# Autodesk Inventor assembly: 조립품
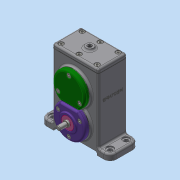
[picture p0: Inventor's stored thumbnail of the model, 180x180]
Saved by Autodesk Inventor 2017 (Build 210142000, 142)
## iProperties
Part Number: 조립품
Material: 일반
Document SubType Name: Assembly
Designer: 222
Mass: 1084.21 g
Surface Area: 1575.48 cm^2
Volume: 385.029 cm^3
Density: 2.81592 g/cm^3
Author: 222
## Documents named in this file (24)
- C:\Users\222\Desktop\600506V1061\조립품.iam
- C:\Users\222\Desktop\600506V1061\Ű 4 x 4 x 12.ipt
- C:\Users\222\Desktop\600506V1061\Ű 5 x 5 x 12.ipt
- C:\Users\222\Desktop\600506V1061\개스킷 A.ipt
- C:\Users\222\Desktop\600506V1061\개스킷 B.ipt
- C:\Users\222\Desktop\600506V1061\개스킷 C.ipt
- C:\Users\222\Desktop\600506V1061\베어링 6001.ipt
- 베어링 6001.ipt
- C:\Users\222\Desktop\600506V1061\베어링 6002.ipt
- 베어링 6002.ipt
- C:\Users\222\Desktop\600506V1061\본체.ipt
- C:\Users\222\Desktop\600506V1061\볼트 M4.ipt
- C:\Users\222\Desktop\600506V1061\스퍼기어 A.ipt
- C:\Users\222\Desktop\600506V1061\스퍼기어 B.ipt
- C:\Users\222\Desktop\600506V1061\오일 실 10 20 7.ipt
- C:\Users\222\Desktop\600506V1061\오일 실 12 22 7.ipt
- C:\Users\222\Desktop\600506V1061\축 A.ipt
- C:\Users\222\Desktop\600506V1061\축 B.ipt
- C:\Users\222\Desktop\600506V1061\칼라.ipt
- C:\Users\222\Desktop\600506V1061\커버 A.ipt
- C:\Users\222\Desktop\600506V1061\커버 B.ipt
- C:\Users\222\Desktop\600506V1061\커버 C.ipt
- C:\Users\222\Desktop\600506V1061\커버 D.ipt
- C:\Users\222\Desktop\600506V1061\커버 E.ipt
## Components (7 placed, 5 different names)
1. Ű 4 x 4 x 12:1
2. Ű 5 x 5 x 12:1
3. 개스킷 A:1
4. 개스킷 B:1
5. 개스킷 C:1
6. 개스킷 B:2
7. 개스킷 B:3
